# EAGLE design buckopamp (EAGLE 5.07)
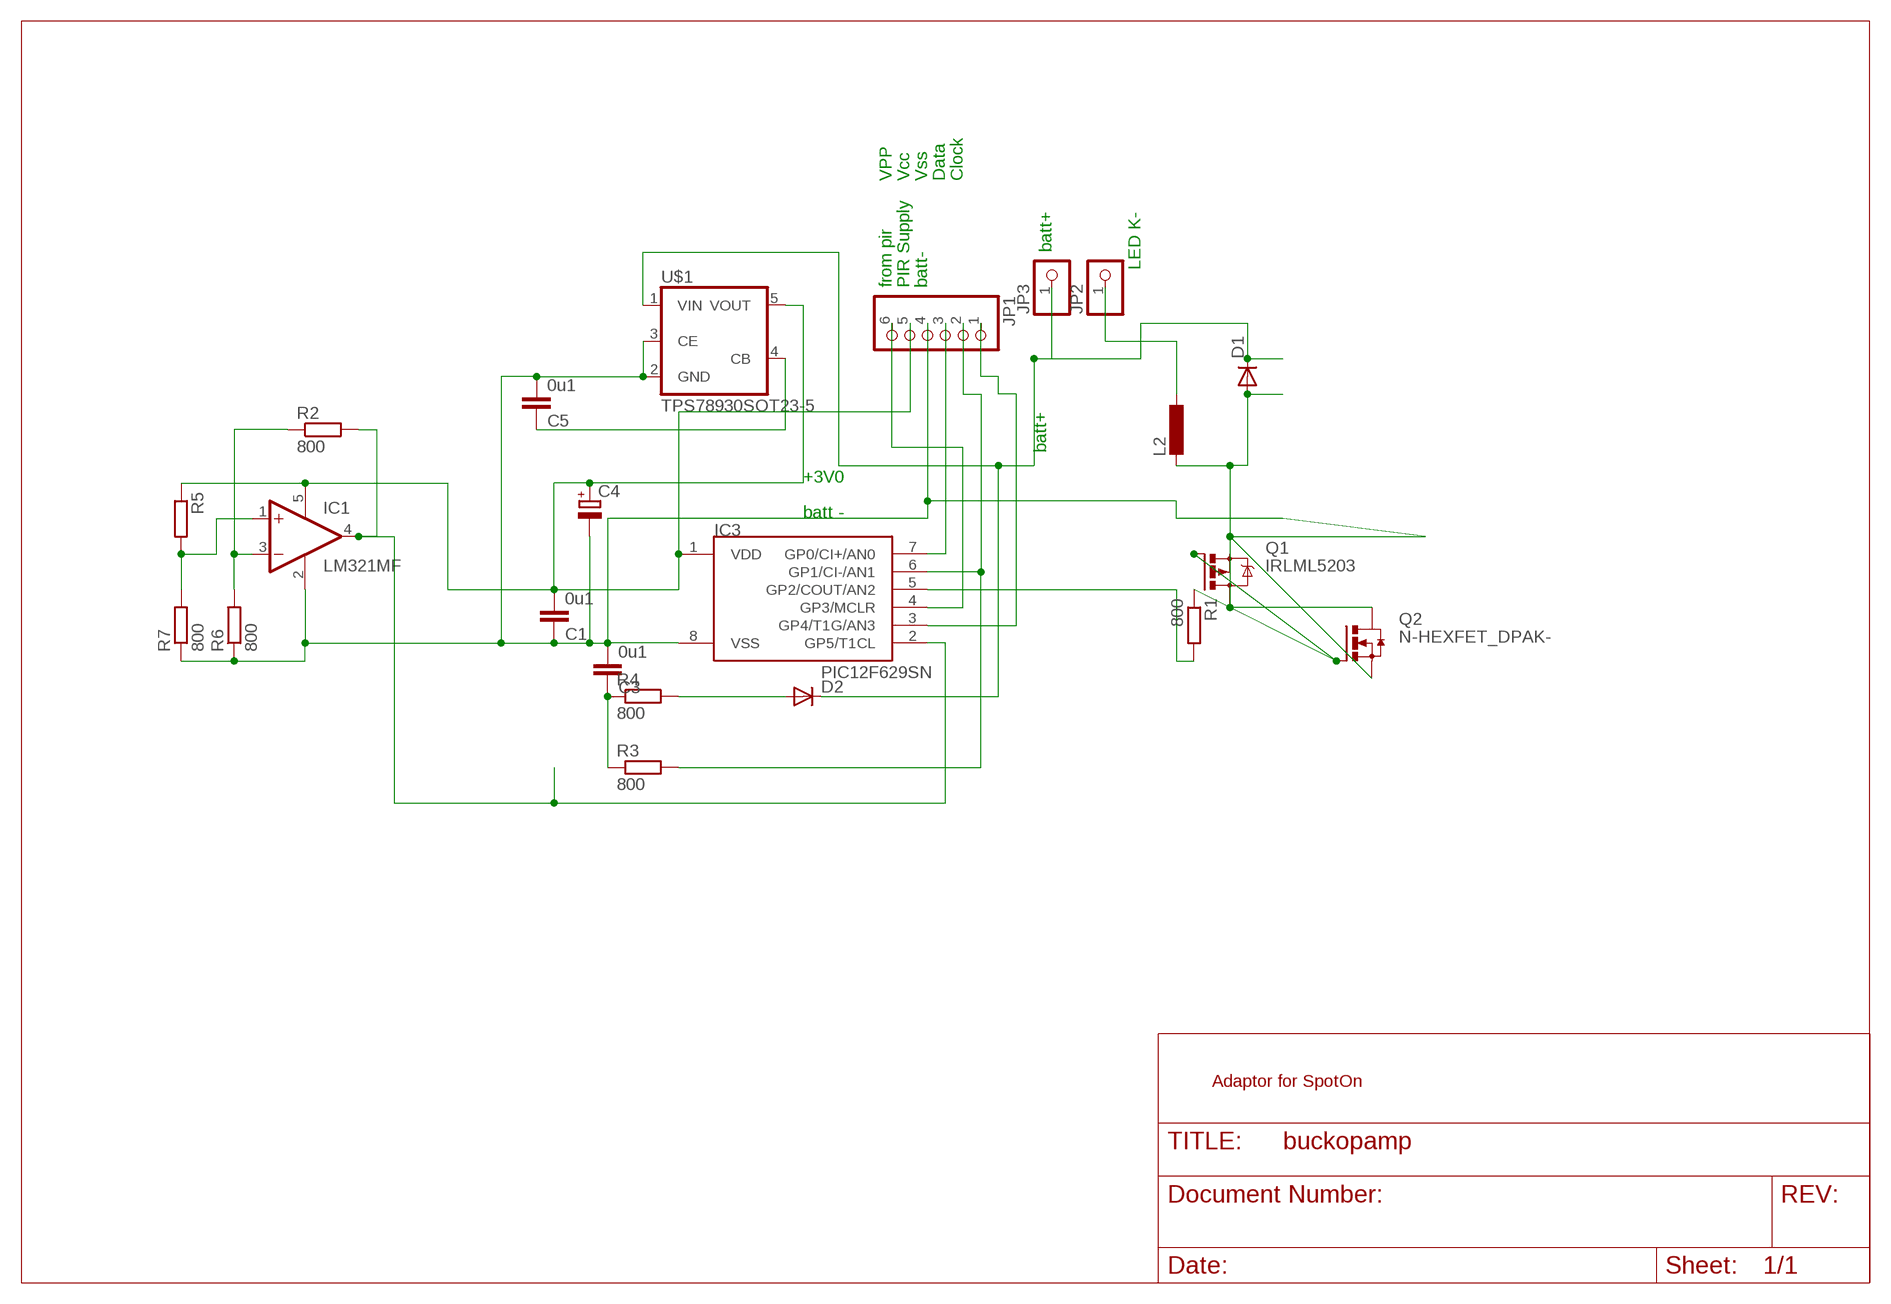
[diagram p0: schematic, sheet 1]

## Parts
C1  0u1  C-EUC1206  [C1206]
C3  0u1  C-EUC1206  [C1206]
C4  CPOL-EUSMCA  [SMC_A]
C5  0u1  C-EUC1206  [C1206]
D1  DIODE-SMC  [SMC]
D2  DIODE-MINIMELF  [MINIMELF]
IC1  LM321MF  [SOT23-5]
IC3  PIC12F629SN  [SO-08]
JP1  PINHD-1X6  [1X06BOX]
JP2  PINHD-1X11X0.4  [1X01]
JP3  PINHD-1X11X0.4  [1X01]
L2  L-EUOPEN  [OPEN5]
Q1  IRLML5203  [MICRO3]
Q2  N-HEXFET_DPAK-  [TO252]
R1  800  R-EU_R1206  [R1206]
R2  800  R-EU_R1206  [R1206]
R3  800  R-EU_R1206  [R1206]
R4  800  R-EU_R1206  [R1206]
R5  R-EU_0411/3V  [0411V]
R6  800  R-EU_R1206  [R1206]
R7  800  R-EU_R1206  [R1206]
U$1  TPS78930SOT23-5  [SOT25]

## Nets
HOT: D1.A L2.2 Q1.3(D) Q2.3(D)
N$1: IC1.3(-IN) R2.1 R6.2
N$2: IC1.4(OUT) IC3.2(GP5/T1CL) R2.2
N$3: D1.C D2.C JP3.1 U$1.1(VIN)
N$4: IC3.6(GP1/CI-/AN1) JP1.2 R3.2
N$5: C5.1 U$1.4(CB)
N$6: JP2.1 L2.1
N$7: C3.1 R3.1 R4.1
N$8: IC1.1(+IN) R5.2 R7.2
N$9: D2.A R4.2
N$12: Q1.1(G) Q2.1(G) R1.1
N$14: IC3.7(GP0/CI+/AN0) JP1.3
N$16: IC3.5(GP2/COUT/AN2) R1.2
N$17: IC3.3(GP4/T1G/AN3) JP1.1
V3: C1.2 C4.+ IC1.5(V+) IC3.1(VDD) JP1.5 R5.1 U$1.5(VOUT)
VPP: IC3.4(GP3/MCLR) JP1.6
VSS: C1.1 C3.2 C4.- C5.2 IC1.2(V-) IC3.8(VSS) JP1.4 Q1.2(S) Q2.2(S) R6.1 R7.1 U$1.2(GND) U$1.3(CE)

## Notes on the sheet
- VPP | Vcc | Vss | Data | Clock
- batt+
- LED K-
- from pir | PIR Supply | batt-
- batt+
- +3V0
- batt -
- Adaptor for SpotOn

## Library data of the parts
C1 C3 C5 = rcl:C-EU: CAPACITOR, European symbol
C4 = rcl(2):CPOL-EU: POLARIZED CAPACITOR, European symbol
D1 = diode:DIODE-: DIODE
D2 = diode-1:DIODE-: DIODE
IC1 = linear:LM321?*: Low Power Single Op Amp Source: http://cache.national.com/ds/LM/LM321.pdf
IC3 = microchip-3:PIC12F6*: uPC nW 1k Program Flash memory 2x Timer Comparator 10b A/D converter/ 4xIN
JP1 = pinhead:PINHD-1X6: PIN HEADER
JP2 JP3 = pinhead:PINHD-1X1: PIN HEADER
L2 = rcl:L-EU: INDUCTOR, European symbol
Q1 = transistor-power:IRLML5203: HEXFET P-Channel Power MOSFET
Q2 = transistor-power:N-HEXFET_?-*: HEXFET® Power MOSFET
R1-R7 = rcl:R-EU_: RESISTOR, European symbol
U$1 = v-reg:TPS78930

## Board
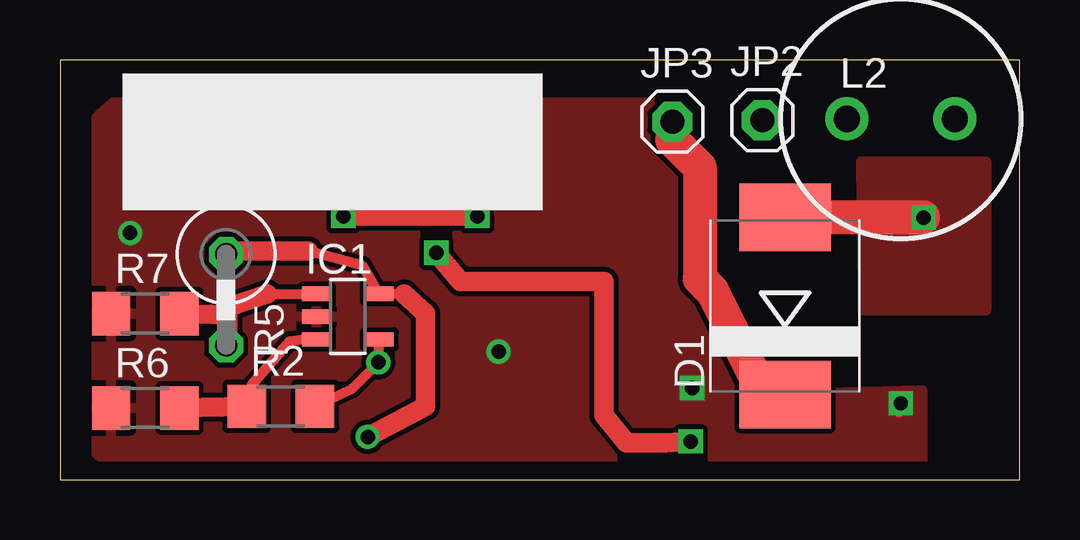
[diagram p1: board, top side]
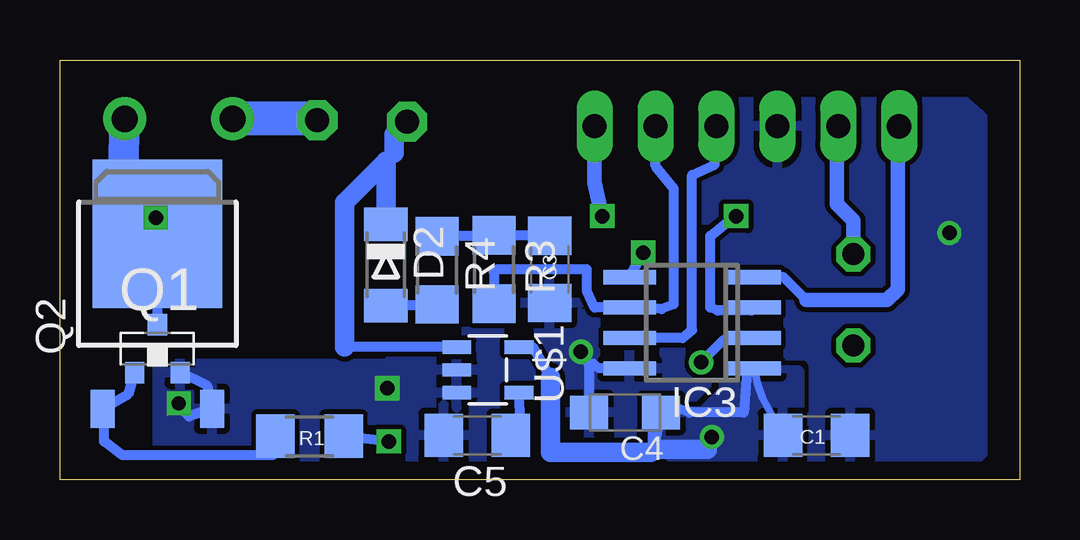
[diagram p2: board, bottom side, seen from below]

Size 40 x 17.5 mm. Coordinates in mm from the lower left corner, seen from the top.
Outline: 0,0 40,0 40,17.5 0,17.5 0,0
Copper layers (1*16): Top 0.035mm / dielectric 1.5mm / Bottom 0.035mm
Design rules "default *": minimum track width 10mil, minimum drill 14mil, track to track 8mil, track to pad 8mil, pad to pad 8mil, via to via 8mil, smd to smd 8mil, copper to edge 30mil, drill to drill 8mil, minimum pad ring 10mil, minimum via ring 8mil, stop-mask expansion 4mil, vias tented up to drill 0mil, thermal gap 10mil

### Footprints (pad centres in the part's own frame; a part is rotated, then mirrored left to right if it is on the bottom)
C1206 = smd 1.6 x 1.8: 1 -1.4,0; 2 1.4,0
SMC_A = smd 1.6 x 1.4: + -1.5,0; - 1.5,0
SMC = smd 2.8 x 3.8: A 3.7,0; C -3.7,0
MINIMELF = smd 1.4 x 1.8: A 1.7,0; C -1.7,0
SOT23-5 = smd 0.6 x 1.2: 1 -0.95,-1.306; 2 0,-1.306; 3 0.95,-1.306; 4 0.95,1.306; 5 -0.95,1.306
SO-08 = smd 0.6 x 2.2: 1 -1.905,-2.6; 2 -0.635,-2.6; 3 0.635,-2.6; 4 1.905,-2.6; 5 1.905,2.6; 6 0.635,2.6; 7 -0.635,2.6; 8 -1.905,2.6
1X06BOX = drill 1 long: 1 -6.35,0; 2 -3.81,0; 3 -1.27,0; 4 1.27,0; 5 3.81,0 | drill 1.016 long: 6 6.35,0
1X01 = drill 1 pad 1.676 octagon: 1 0,0
OPEN5 = drill 1.1 pad 1.778 round: 1 -2.25,0; 2 2.25,0
MICRO3 = smd 0.8 x 0.9: 1 -0.95,-1; 2 0.95,-1; 3 0,1
TO252 = smd 1 x 1.6: 1 -2.28,-3.53; 2 2.28,-3.53 | smd 5.4 x 6.2: 3 0,3.77
R1206 = smd 1.6 x 1.803: 1 -1.422,0; 2 1.422,0
0411V = drill 0.914 octagon: 1 -2.54,0; 2 1.27,0
SOT25 = smd 0.55 x 1.2: 1 -0.95,-1.3; 2 0,-1.3; 3 0.95,-1.3; 4 0.95,1.3; 5 -0.95,1.3

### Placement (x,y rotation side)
C1  8.46,1.84 180 bottom
C3  19.58,8.76 270 bottom
C4  16.45,2.79 180 bottom
C5  22.61,1.84 180 bottom
D1  30.23,7.24 90 top
D2  26.42,8.95 270 bottom
IC1  12,6.79 270 top
IC3  13.65,6.54 90 bottom
JP1  11.37,14.73 180 top
JP2  29.27,14.99 0 top
JP3  25.53,14.92 0 top
L2  35.05,15.05 0 top
Q1  35.94,5.46 0 bottom
Q2  35.94,6.48 0 bottom
R1  29.6,1.81 0 bottom
R2  9.21,3.05 0 top
R3  21.91,8.76 270 bottom
R4  24.28,8.73 270 bottom
R5  6.92,6.86 270 top
R6  3.56,2.98 0 top
R7  3.56,6.92 0 top
U$1  22.16,4.57 270 bottom

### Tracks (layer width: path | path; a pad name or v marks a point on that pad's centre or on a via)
HOT  (via drill 0.6)
  Top 0.406: 35.99,10.94 v36.01,10.92
  Top 1.422: D1.A 35.99,10.94
  Bottom 0.406: v36.01,10.92 36.89,11.87 37.02,12.19 37.37,12.89 | Q2.3 Q1.3 35.94,6.4
  Bottom 1.27: 37.37,12.89 L2.2
  Bottom 1.422: v36.01,10.92 36.01,10.31 Q2.3
  pour Top: 33.4,13.27 38.61,13.27 38.61,7.05 33.46,7.05 33.46,7.87
N$1
  Top 0.406: IC1.3 10.1,5.84 9.59,5.78 8,3.96 R2.1
  Top 0.813: R6.2 R2.1
N$2  (via drill 0.6)
  Top 0.406: IC1.4 13.31,4.93 v13.27,4.89 12.19,3.81 R2.2
  Bottom 0.406: v13.27,4.89 12.32,5.84 11.12,5.84 IC3.2
N$3
  Top 0.406: 29.21,3.81 D1.C
  Top 1.422: JP3.1 25.53,14.16 26.67,13.02 26.67,8.38 27.18,7.87 29.21,3.81
  Bottom 0.406: U$1.1 28.13,5.52 | 26.07,14.38 JP3.1 | 26.42,13.27 26.07,13.62
  Bottom 0.813: 28.13,5.52 28.13,11.56 26.42,13.27 D2.C | 26.07,13.62 26.07,14.38
N$4
  Bottom 0.406: R3.2 21.91,8.64 21.78,8.76 18.03,8.76 18.03,7.87 17.72,7.18 IC3.6 14.92,7.11 14.41,7.3 14.41,12.13 15.18,13.08 JP1.2
N$5
  Bottom 0.406: U$1.4 20.8,2.38 C5.1
N$6
  Bottom 0.406: JP2.1 29.34,15.05
  Bottom 1.422: 29.34,15.05 L2.1
N$7
  Bottom 0.406: R4.1 21.95,10.15 R3.1 19.61,10.19 C3.1
N$8
  Top 0.406: 8.63,7.75 IC1.1 | 6.99,6.86 6.99,7.18 | 6.99,5.59 R5.2
  Top 0.813: 6.99,7.18 8.63,7.75 | 6.99,5.59 6.99,6.86 R7.2
N$9
  Bottom 0.406: D2.A 24.33,7.25 R4.2
N$12
  Bottom 0.406: Q1.1 37.15,3.58 Q2.1 38.16,2.18 38.16,1.59 37.4,1.02 31.11,1.02 30.45,1.49 R1.1
N$14
  Bottom 0.406: IC3.7 14.03,5.91 13.65,6.22 13.65,12.7 12.7,13.14 12.7,15.18 JP1.3
N$16  (via drill 0.6)
  Top 0.813: v26.29,1.59 25.21,1.52 23.62,1.52 22.67,2.67 22.67,8.26 16.7,8.26 v15.68,9.46
  Bottom 0.406: R1.2 26.54,1.62 v26.29,1.59 | v15.68,9.46 IC3.5
N$17  (via drill 0.6)
  Top 0.813: v11.81,10.99 v17.4,10.99
  Bottom 0.406: v11.81,10.99 11.81,11.05 12.89,10.16 12.89,7.18 12.57,7.05 11.18,7.05 IC3.3
  Bottom 0.61: JP1.1 17.72,12.38 v17.4,10.99
V3  (via drill 0.6)
  Top 0.406: 10.35,9.53 12.61,8.92 IC1.5 14.35,7.75 | 7.24,9.53 R5.1
  Top 0.813: 10.35,9.53 7.24,9.53 | 14.35,7.75 15.24,6.92 15.24,3.05 v12.83,1.78
  Bottom 0.305: 11.3,4.64 IC3.1 10.92,4 10.71,3.41 C1.2
  Bottom 0.406: 7.62,15.18 JP1.5 | C4.+ 14.95,3.21 13.78,2.79 11.49,2.79 11.37,4.51 11.18,4.51 IC3.1 | C4.+ 15.14,1.88 15.3,1.02 | 19.56,4.25 20.29,5.52 U$1.5 | 13.02,1.27 v12.83,1.78 | 15.18,1.27 15.3,1.21 15.3,2.44 C4.+
  Bottom 0.61: 7.62,15.18 7.62,11.49 6.92,10.79 R5.1
  Bottom 0.813: 19.56,4.25 19.56,1.14 15.37,1.14 15.3,1.21 | 15.18,1.27 13.02,1.27
  pour Bottom: 9.97,4.57 9.21,4.57 9.21,0.83 14.35,0.76 14.92,1.27 14.92,2.86 13.21,2.86 12.32,3.75 12.32,4.13 11.94,4.51
VPP
  Bottom 0.406: IC3.4 9.84,8.45 8.89,7.49 | 5.08,15.18 JP1.6
  Bottom 0.61: 8.89,7.49 5.52,7.49 5.08,7.94 5.08,15.18
VSS  (via drill 0.6)
  Top 0.406: v35.05,3.17 34.99,2.79
  Bottom 0.406: C3.2 18.89,6.95 | 17.78,4.83 17.52,4.64 IC3.8 | 17.78,4.83 17.97,4.83 | Q1.2 33.85,3.9 Q2.2 34.63,2.63 v35.05,3.17 | C4.- 17.95,4.66 17.78,4.83
  other vias: 2.92,10.29 18.29,5.33 26.35,3.81
  pour Top: 2.22,15.75 25.34,15.75 26.42,14.67 28.26,4.38 28.45,3.24 30.99,3.62 35.94,3.75 35.94,0.57 31.05,0.38 2.22,0.38 1.52,1.08 1.52,15.11 1.59,15.18 1.65,15.18 1.65,15.24
  pour Bottom (rank 3): 2.22,15.75 25.34,15.75 26.42,14.67 26.23,4.83 35.94,4.83 35.94,0.57 31.05,0.38 2.22,0.38 1.52,1.08 1.52,15.11 1.59,15.18 1.65,15.18 1.65,15.24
